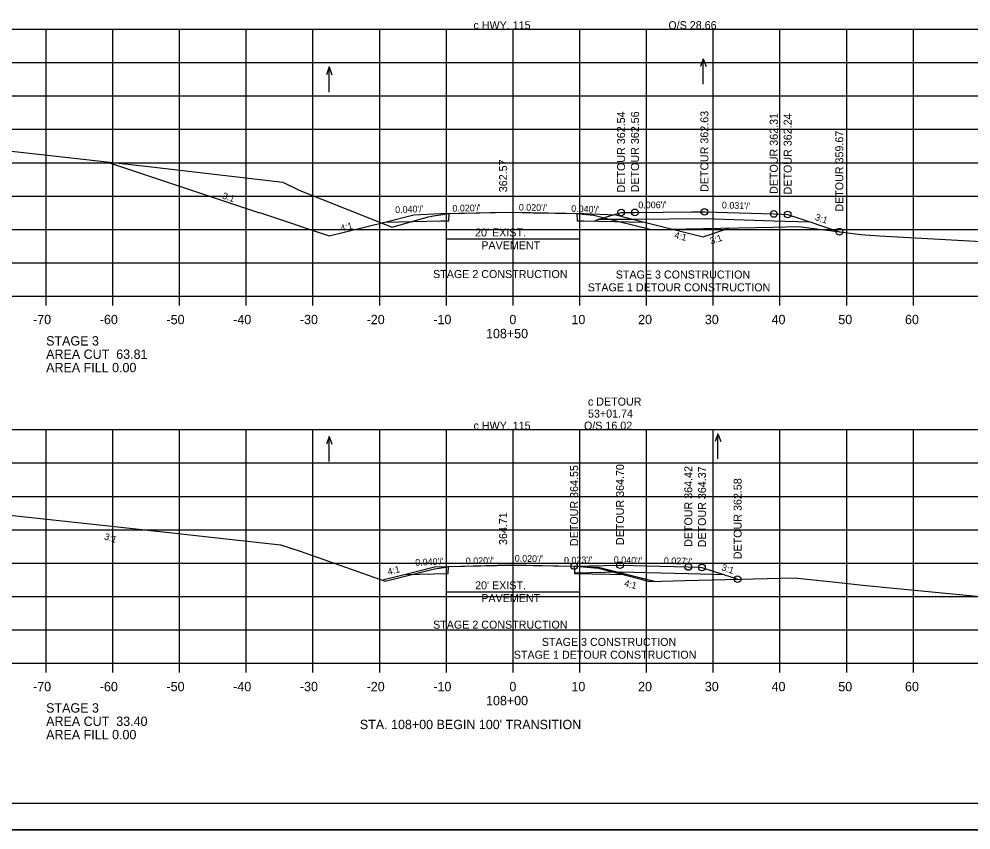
# Model space of a CAD drawing. Extents: x 1630712 to 1632516, y 782146 to 785403.
# Drawn here: x 1632258.9 to 1632401.6, y 783696.6 to 783818.1 of the extents above; entities that cross this region are included whole.
import ezdxf

# ---------------------------------------------------------------- set-up
doc = ezdxf.new("R2010")
doc.units = 0
for name, color, linetype in [('Notes', 7, 'Continuous'), ('R_Alt Surface', 7, 'Continuous'), ('R_Annot', 7, 'Continuous'), ('R_Axis', 7, 'Continuous'), ('R_Axis Annot', 7, 'Continuous'), ('R_Border', 7, 'Continuous'), ('R_Detour Subgrade', 7, 'Continuous'), ('R_Detour Surface', 7, 'Continuous'), ('R_Exist Surface', 7, 'Continuous'), ('R_Fin Surface', 7, 'Continuous'), ('R_Grid', 7, 'Continuous'), ('R_No Plot', 7, 'Continuous'), ('R_Water Annot', 7, 'Continuous'), ('R_Xsect Elev', 7, 'Continuous'), ('R_Xsect Elev Detour', 7, 'Continuous'), ('R_Xsect Slope', 7, 'Continuous')]:
    doc.layers.add(name, color=color, linetype=linetype)

msp = doc.modelspace()

# ---------------------------------------------------------------- linework, layer by layer
at = {"layer": 'Notes'}
for p, q in [((1632322.96, 783783.5), (1632322.96, 783786.9)), ((1632342.96, 783783.5), (1632342.96, 783786.9)), ((1632322.96, 783785.2), (1632342.96, 783785.2)), ((1632322.96, 783730.63), (1632322.96, 783734.03)), ((1632342.96, 783730.63), (1632342.96, 783734.03)), ((1632322.96, 783732.33), (1632342.96, 783732.33))]:
    msp.add_line(p, q, dxfattribs=at)
at = {"layer": 'R_Alt Surface'}
for points in [[(1632313.73, 783787.73), (1632322.12, 783787.9), (1632323.31, 783787.92), (1632323.36, 783788.98), (1632332.62, 783789.2), (1632342.52, 783788.99), (1632342.57, 783787.93), (1632343.53, 783787.9), (1632352.65, 783787.72)], [(1632316.67, 783734.92), (1632323.24, 783735.05), (1632323.29, 783736.12), (1632332.54, 783736.34), (1632342.1, 783736.17), (1632342.15, 783735.06), (1632350.16, 783734.9)]]:
    msp.add_lwpolyline(points, dxfattribs=at)
at = {"layer": 'R_Axis'}
for p, q in [((1632212.96, 783776.62), (1632492.96, 783776.62)), ((1632262.96, 783775.22), (1632262.96, 783776.62)), ((1632272.96, 783775.22), (1632272.96, 783776.62)), ((1632282.96, 783775.22), (1632282.96, 783776.62)), ((1632292.96, 783775.22), (1632292.96, 783776.62)), ((1632302.96, 783775.22), (1632302.96, 783776.62)), ((1632312.96, 783775.22), (1632312.96, 783776.62)), ((1632322.96, 783775.22), (1632322.96, 783776.62)), ((1632332.96, 783775.22), (1632332.96, 783776.62)), ((1632342.96, 783775.22), (1632342.96, 783776.62)), ((1632352.96, 783775.22), (1632352.96, 783776.62)), ((1632362.96, 783775.22), (1632362.96, 783776.62)), ((1632372.96, 783775.22), (1632372.96, 783776.62)), ((1632382.96, 783775.22), (1632382.96, 783776.62)), ((1632392.96, 783775.22), (1632392.96, 783776.62)), ((1632212.96, 783721.62), (1632492.96, 783721.62)), ((1632262.96, 783720.22), (1632262.96, 783721.62)), ((1632272.96, 783720.22), (1632272.96, 783721.62)), ((1632282.96, 783720.22), (1632282.96, 783721.62)), ((1632292.96, 783720.22), (1632292.96, 783721.62)), ((1632302.96, 783720.22), (1632302.96, 783721.62)), ((1632312.96, 783720.22), (1632312.96, 783721.62)), ((1632322.96, 783720.22), (1632322.96, 783721.62)), ((1632332.96, 783720.22), (1632332.96, 783721.62)), ((1632342.96, 783720.22), (1632342.96, 783721.62)), ((1632352.96, 783720.22), (1632352.96, 783721.62)), ((1632362.96, 783720.22), (1632362.96, 783721.62)), ((1632372.96, 783720.22), (1632372.96, 783721.62)), ((1632382.96, 783720.22), (1632382.96, 783721.62)), ((1632392.96, 783720.22), (1632392.96, 783721.62))]:
    msp.add_line(p, q, dxfattribs=at)
at = {"layer": 'R_Border'}
msp.add_line((1632511.14, 783700.62), (1632194.96, 783700.62), dxfattribs=at)
at = {"layer": 'R_Detour Subgrade'}
for points in [[(1632345.82, 783788.13), (1632351.22, 783788.17), (1632361.63, 783788.25), (1632372.03, 783787.93), (1632377.43, 783787.76)], [(1632342.1, 783736.17), (1632342.15, 783735.17), (1632348.98, 783735.32), (1632359.22, 783735.04), (1632364.54, 783734.89)], [(1632342.1, 783736.17), (1632342.15, 783735.17), (1632348.98, 783735.32), (1632359.22, 783735.04), (1632364.54, 783734.89)]]:
    msp.add_lwpolyline(points, dxfattribs=at)
at = {"layer": 'R_Detour Surface'}
for points in [[(1632345.13, 783787.87), (1632345.82, 783788.13), (1632349.13, 783789.16), (1632349.14, 783789.16), (1632349.15, 783789.16), (1632349.23, 783789.16), (1632349.49, 783789.16), (1632349.54, 783789.16), (1632351.22, 783789.17), (1632359.68, 783789.24), (1632361.63, 783789.25), (1632361.63, 783789.25), (1632372.03, 783788.93), (1632373.12, 783788.89), (1632374.11, 783788.86), (1632376.09, 783788.2), (1632377.43, 783787.76), (1632377.64, 783787.69), (1632378.05, 783787.55), (1632378.86, 783787.28), (1632381.86, 783786.28)], [(1632342.1, 783736.17), (1632348.85, 783736.32), (1632348.98, 783736.32), (1632349, 783736.32), (1632349.01, 783736.32), (1632349.03, 783736.32), (1632352.91, 783736.21), (1632359.22, 783736.04), (1632360.8, 783736), (1632361.27, 783735.98), (1632363.53, 783735.23), (1632364.54, 783734.89), (1632364.75, 783734.82), (1632365.15, 783734.69), (1632366.04, 783734.39), (1632366.61, 783734.2)]]:
    msp.add_lwpolyline(points, dxfattribs=at)
at = {"layer": 'R_Exist Surface'}
for points in [[(1632248.39, 783799.37), (1632278.73, 783795.99), (1632298.42, 783793.71), (1632300.97, 783792.45), (1632314.82, 783786.94), (1632320.23, 783788.49), (1632321.33, 783788.71), (1632322.07, 783788.8), (1632322.69, 783788.89), (1632323.36, 783788.98), (1632329.45, 783789.13), (1632332.62, 783789.2), (1632335.98, 783789.12), (1632342.52, 783788.99), (1632343.41, 783788.91), (1632345.06, 783788.77), (1632348.42, 783787.91), (1632353.7, 783786.62), (1632371.91, 783786.97), (1632375.72, 783787.07), (1632385.08, 783785.87), (1632385.75, 783785.79), (1632387.86, 783785.68), (1632423, 783783.71)], [(1632249.13, 783744.72), (1632273.69, 783742.03), (1632298.1, 783739.36), (1632301.03, 783738.39), (1632313.8, 783733.93), (1632319.57, 783735.36), (1632321.19, 783735.74), (1632322.85, 783736.03), (1632323.29, 783736.12), (1632330.98, 783736.3), (1632332.54, 783736.34), (1632334.1, 783736.31), (1632342.1, 783736.17), (1632342.88, 783736.1), (1632345.78, 783735.86), (1632351.76, 783734.3), (1632353.45, 783733.85), (1632358.72, 783733.99), (1632375.15, 783734.43), (1632381.34, 783733.77), (1632385.36, 783733.3), (1632403.49, 783731.55)]]:
    msp.add_lwpolyline(points, dxfattribs=at)
at = {"layer": 'R_Fin Surface'}
for points in [[(1632272.14, 783796.72), (1632294.81, 783789.17), (1632294.88, 783789.15), (1632295.08, 783789.08), (1632305.38, 783785.65), (1632313.73, 783787.73), (1632318.07, 783788.82), (1632322.12, 783788.98), (1632332.96, 783789.2), (1632343.53, 783788.99), (1632348.37, 783788.79), (1632352.65, 783787.72), (1632361.46, 783785.52), (1632365.43, 783786.84)], [(1632313.36, 783734.08), (1632313.79, 783734.2), (1632316.67, 783734.92), (1632321.18, 783736.05), (1632323.28, 783736.13), (1632332.96, 783736.33), (1632342.09, 783736.14), (1632345.78, 783736), (1632350.16, 783734.9), (1632353.96, 783733.95), (1632354.2, 783733.87)]]:
    msp.add_lwpolyline(points, dxfattribs=at)
at = {"layer": 'R_Grid'}
for p, q in [((1632212.96, 783816.62), (1632492.96, 783816.62)), ((1632262.96, 783776.62), (1632262.96, 783816.62)), ((1632272.96, 783776.62), (1632272.96, 783816.62)), ((1632282.96, 783776.62), (1632282.96, 783816.62)), ((1632292.96, 783776.62), (1632292.96, 783816.62)), ((1632302.96, 783776.62), (1632302.96, 783816.62)), ((1632312.96, 783776.62), (1632312.96, 783816.62)), ((1632322.96, 783776.62), (1632322.96, 783816.62)), ((1632332.96, 783776.62), (1632332.96, 783816.62)), ((1632342.96, 783776.62), (1632342.96, 783816.62)), ((1632352.96, 783776.62), (1632352.96, 783816.62)), ((1632362.96, 783776.62), (1632362.96, 783816.62)), ((1632372.96, 783776.62), (1632372.96, 783816.62)), ((1632382.96, 783776.62), (1632382.96, 783816.62)), ((1632392.96, 783776.62), (1632392.96, 783816.62)), ((1632212.96, 783811.62), (1632492.96, 783811.62)), ((1632212.96, 783806.62), (1632492.96, 783806.62)), ((1632212.96, 783801.62), (1632492.96, 783801.62)), ((1632212.96, 783796.62), (1632492.96, 783796.62)), ((1632212.96, 783791.62), (1632492.96, 783791.62)), ((1632212.96, 783786.62), (1632492.96, 783786.62)), ((1632212.96, 783781.62), (1632492.96, 783781.62)), ((1632212.96, 783776.62), (1632492.96, 783776.62)), ((1632212.96, 783756.62), (1632492.96, 783756.62)), ((1632262.96, 783721.62), (1632262.96, 783756.62)), ((1632272.96, 783721.62), (1632272.96, 783756.62)), ((1632282.96, 783721.62), (1632282.96, 783756.62)), ((1632292.96, 783721.62), (1632292.96, 783756.62)), ((1632302.96, 783721.62), (1632302.96, 783756.62)), ((1632312.96, 783721.62), (1632312.96, 783756.62)), ((1632322.96, 783721.62), (1632322.96, 783756.62)), ((1632332.96, 783721.62), (1632332.96, 783756.62)), ((1632342.96, 783721.62), (1632342.96, 783756.62)), ((1632352.96, 783721.62), (1632352.96, 783756.62)), ((1632362.96, 783721.62), (1632362.96, 783756.62)), ((1632372.96, 783721.62), (1632372.96, 783756.62)), ((1632382.96, 783721.62), (1632382.96, 783756.62)), ((1632392.96, 783721.62), (1632392.96, 783756.62)), ((1632212.96, 783751.62), (1632492.96, 783751.62)), ((1632212.96, 783746.62), (1632492.96, 783746.62)), ((1632212.96, 783741.62), (1632492.96, 783741.62)), ((1632212.96, 783736.62), (1632492.96, 783736.62)), ((1632212.96, 783731.62), (1632492.96, 783731.62)), ((1632212.96, 783726.62), (1632492.96, 783726.62)), ((1632212.96, 783721.62), (1632492.96, 783721.62))]:
    msp.add_line(p, q, dxfattribs=at)
at = {"layer": 'R_No Plot'}
msp.add_line((1632182.56, 783696.64), (1632515.9, 783696.64), dxfattribs=at)
msp.add_lwpolyline([(1632182.56, 783909.97), (1632515.9, 783909.97), (1632515.9, 783696.63), (1632182.56, 783696.63)], close=True, dxfattribs=at)
for centre in [(1632349.14, 783789.16), (1632351.22, 783789.17), (1632361.63, 783789.25), (1632372.03, 783788.93), (1632374.11, 783788.86), (1632381.86, 783786.28), (1632342.1, 783736.17), (1632348.98, 783736.32), (1632359.22, 783736.04), (1632361.27, 783735.98), (1632366.61, 783734.2)]:
    msp.add_circle(centre, 0.5, dxfattribs=at)
at = {"layer": 'R_Water Annot'}
for p, q in [((1632305.38, 783810.96), (1632304.96, 783809.8)), ((1632305.38, 783807.19), (1632305.38, 783810.96)), ((1632305.38, 783810.96), (1632305.8, 783809.8)), ((1632361.46, 783812.16), (1632361.04, 783811.01)), ((1632361.46, 783808.39), (1632361.46, 783812.16)), ((1632361.46, 783812.16), (1632361.88, 783811.01)), ((1632305.38, 783755.59), (1632304.96, 783754.44)), ((1632305.38, 783751.82), (1632305.38, 783755.59)), ((1632305.38, 783755.59), (1632305.8, 783754.44)), ((1632363.66, 783755.99), (1632363.24, 783754.84)), ((1632363.66, 783752.22), (1632363.66, 783755.99)), ((1632363.66, 783755.99), (1632364.08, 783754.84))]:
    msp.add_line(p, q, dxfattribs=at)

# ---------------------------------------------------------------- texts
at = {"layer": 'Notes'}
for s, p in [('c HWY. 115', (1632327.02, 783816.62)), ('O/S 28.66', (1632356.23, 783816.62)), ("20' EXIST.", (1632327.26, 783785.56)), ('PAVEMENT', (1632328.19, 783783.64)), ('STAGE 2 CONSTRUCTION', (1632320.96, 783779.33)), ('STAGE 3 CONSTRUCTION', (1632348.34, 783779.26)), ('STAGE 1 DETOUR CONSTRUCTION', (1632344.14, 783777.34)), ('c DETOUR', (1632344.17, 783760.22)), ('53+01.74', (1632344.18, 783758.42)), ('c HWY. 115', (1632327.02, 783756.62)), ('O/S 16.02', (1632343.58, 783756.62)), ("20' EXIST.", (1632327.26, 783732.69)), ('PAVEMENT', (1632328.19, 783730.77)), ('STAGE 2 CONSTRUCTION', (1632320.96, 783726.8)), ('STAGE 3 CONSTRUCTION', (1632337.26, 783724.21)), ('STAGE 1 DETOUR CONSTRUCTION', (1632333.06, 783722.29))]:
    msp.add_text(s, height=1.2, dxfattribs=at).set_placement(p)
at = {"layer": 'R_Annot'}
msp.add_text("STA. 108+00 BEGIN 100' TRANSITION", height=1.4, dxfattribs=at).set_placement((1632309.98, 783711.74))
at = {"layer": 'R_Axis Annot'}
for s, p in [('-70', (1632261, 783772.42)), ('-60', (1632271, 783772.42)), ('-50', (1632281, 783772.42)), ('-40', (1632291, 783772.42)), ('-30', (1632301, 783772.42)), ('-20', (1632311, 783772.42)), ('-10', (1632321, 783772.42)), ('0', (1632332.4, 783772.42)), ('10', (1632341.7, 783772.42)), ('20', (1632351.7, 783772.42)), ('30', (1632361.7, 783772.42)), ('40', (1632371.7, 783772.42)), ('50', (1632381.7, 783772.42)), ('60', (1632391.7, 783772.42)), ('108+50', (1632328.9, 783770.32)), ('STAGE 3', (1632262.96, 783769.22)), ('AREA CUT  63.81', (1632262.96, 783767.22)), ('AREA FILL 0.00', (1632262.96, 783765.22)), ('-70', (1632261, 783717.42)), ('-60', (1632271, 783717.42)), ('-50', (1632281, 783717.42)), ('-40', (1632291, 783717.42)), ('-30', (1632301, 783717.42)), ('-20', (1632311, 783717.42)), ('-10', (1632321, 783717.42)), ('0', (1632332.4, 783717.42)), ('10', (1632341.7, 783717.42)), ('20', (1632351.7, 783717.42)), ('30', (1632361.7, 783717.42)), ('40', (1632371.7, 783717.42)), ('50', (1632381.7, 783717.42)), ('60', (1632391.7, 783717.42)), ('108+00', (1632328.9, 783715.32)), ('STAGE 3', (1632262.96, 783714.22)), ('AREA CUT  33.40', (1632262.96, 783712.22)), ('AREA FILL 0.00', (1632262.96, 783710.22))]:
    msp.add_text(s, height=1.4, dxfattribs=at).set_placement(p)
at = {"layer": 'R_Xsect Elev'}
for s, p in [('362.57', (1632332.06, 783792.19)), ('364.71', (1632332.06, 783739.33))]:
    msp.add_text(s, height=1.2, rotation=90, dxfattribs=at).set_placement(p)
at = {"layer": 'R_Xsect Elev Detour'}
for s, p in [('DETOUR 362.54', (1632349.74, 783792.16)), ('DETOUR 362.56', (1632351.82, 783792.17)), ('DETOUR 362.63', (1632362.23, 783792.25)), ('DETOUR 362.31', (1632372.63, 783791.93)), ('DETOUR 362.24', (1632374.71, 783791.86)), ('DETOUR 359.67', (1632382.46, 783789.28)), ('DETOUR 364.55', (1632342.7, 783739.17)), ('DETOUR 364.70', (1632349.58, 783739.32)), ('DETOUR 364.42', (1632359.82, 783739.04)), ('DETOUR 364.37', (1632361.87, 783738.98)), ('DETOUR 362.58', (1632367.21, 783737.2))]:
    msp.add_text(s, height=1.2, rotation=90, dxfattribs=at).set_placement(p)
at = {"layer": 'R_Xsect Slope'}
for s, rotation, p in [('3:1', 341.5651, (1632289.27, 783791.27)), ("0.006'/'", 0.4103, (1632351.73, 783789.78)), ("0.040'/'", 2.2906, (1632315.3, 783789.06)), ("0.020'/'", 1.1458, (1632323.87, 783789.28)), ("0.020'/'", 358.8542, (1632333.8, 783789.45)), ("0.040'/'", 357.7094, (1632341.65, 783789.26)), ("0.031'/'", 358.2079, (1632364.24, 783789.77)), ('3:1', 341.6084, (1632378.14, 783788.05)), ('4:1', 14.0362, (1632307.19, 783786.29)), ('4:1', 345.9638, (1632357.04, 783785.33)), ('3:1', 18.435, (1632362.63, 783784.37)), ('3:1', 341.5651, (1632271.58, 783740.2)), ("0.040'/'", 2.2906, (1632318.3, 783736.22)), ("0.020'/'", 1.1458, (1632325.87, 783736.44)), ("0.020'/'", 358.8542, (1632333.19, 783736.85)), ("0.023'/'", 1.3014, (1632340.6, 783736.53)), ("0.040'/'", 357.7094, (1632348.03, 783736.65)), ("0.027'/'", 358.4235, (1632355.54, 783736.5)), ('4:1', 14.0362, (1632314.27, 783734.82)), ('3:1', 341.5485, (1632364.1, 783735.57)), ('4:1', 345.9638, (1632349.54, 783733.17))]:
    msp.add_text(s, height=1, rotation=rotation, dxfattribs=at).set_placement(p)

doc.saveas('drawing.dxf')
